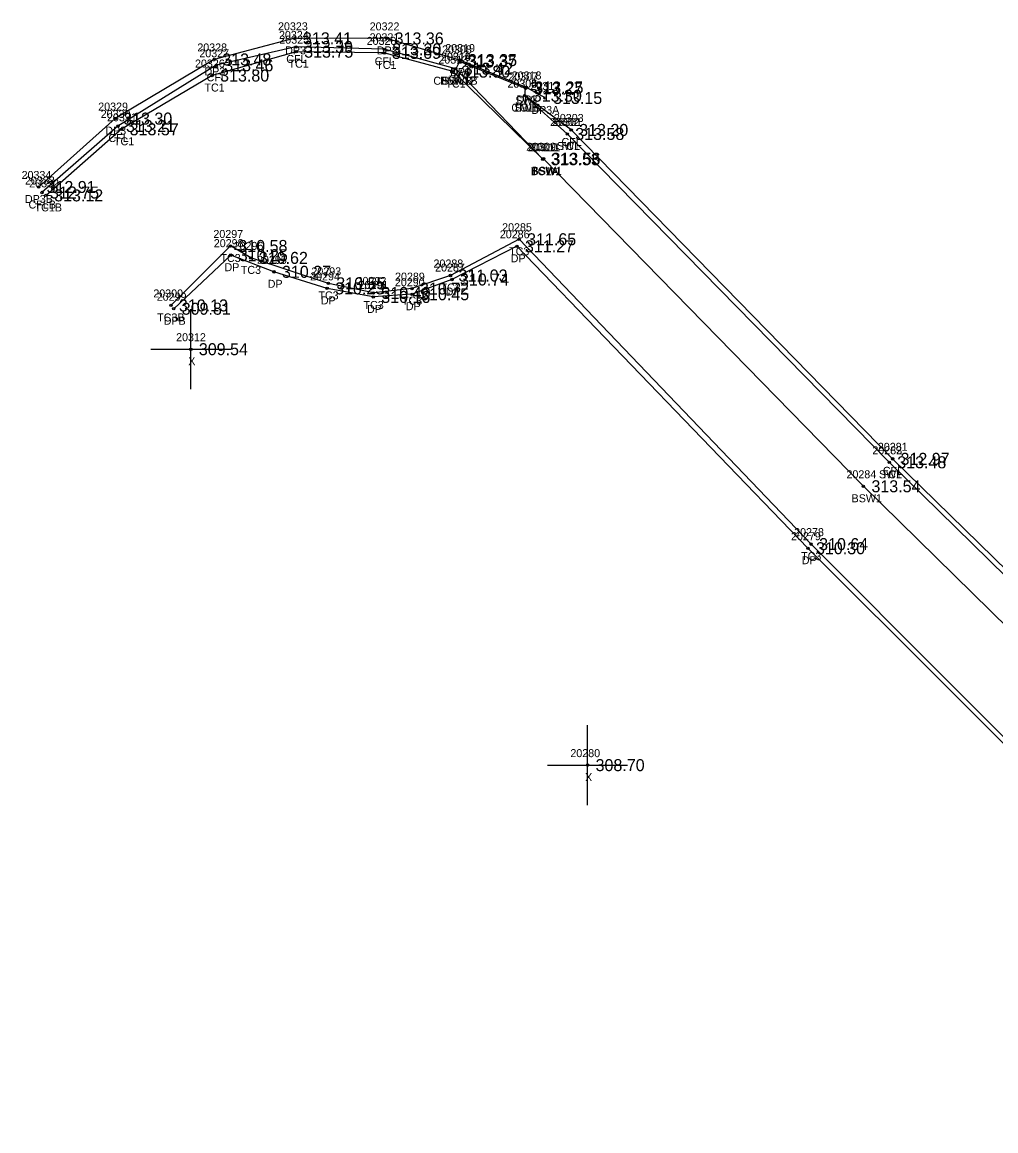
# Model space of a CAD drawing. Extents: x 1970242 to 1971082, y 803104 to 803947.
# Drawn here: x 1970551.6 to 1970673.3, y 803381.9 to 803520.5 of the extents above; entities that cross this region are included whole.
import ezdxf

# ---------------------------------------------------------------- set-up
doc = ezdxf.new("R2010")
doc.units = 0
for name, color, linetype in [('RD_DTM_BkLn2', 7, 'Continuous'), ('RD_EX_Conc', 7, 'Continuous'), ('RD_EX_Conc_txCode', 7, 'Continuous'), ('RD_EX_Driveway', 7, 'Continuous'), ('RD_EX_Driveway_txCode', 7, 'Continuous'), ('RD_EX_Misc', 7, 'Continuous'), ('RD_EX_Misc_txCode', 7, 'Continuous'), ('RD_EX_TX_Conc_ELEV', 7, 'Continuous'), ('RD_EX_TX_Driveway_ELEV', 7, 'Continuous'), ('RD_EX_TX_Misc_ELEV', 7, 'Continuous'), ('RD_SMD_Locator', 7, 'Continuous')]:
    doc.layers.add(name, color=color, linetype=linetype)

msp = doc.modelspace()

# ---------------------------------------------------------------- linework, layer by layer
at = {"layer": 'RD_DTM_BkLn2'}
for points in [[(1970616.66, 803503.34), (1970605.45, 803514.29), (1970596.8, 803516.63), (1970585.83, 803516.78), (1970575.32, 803513.8), (1970564.01, 803507.08), (1970554.57, 803498.82)], [(1970741.86, 803386.33), (1970712.13, 803414.37), (1970659.98, 803465.47), (1970619.72, 803506.5), (1970614.41, 803511.28)], [(1970738.35, 803383.61), (1970734.45, 803382.06), (1970730.21, 803381.92), (1970725.73, 803383.47), (1970721.43, 803385.54), (1970701.8, 803403.54), (1970650.21, 803455.24), (1970613.7, 803493.34), (1970605.12, 803488.81), (1970600.31, 803487.17), (1970595.49, 803486.63), (1970589.85, 803487.83), (1970580.16, 803491.01), (1970577.6, 803492.5), (1970570.17, 803485.07)]]:
    msp.add_lwpolyline(points, dxfattribs=at)
at = {"layer": 'RD_EX_Conc'}
for points in [[(1970605.78, 803514.65), (1970596.84, 803517.08), (1970585.8, 803517.37), (1970575.84, 803515.08), (1970563.55, 803507.49), (1970554.05, 803499.18)], [(1970741.86, 803386.33), (1970712.13, 803414.37), (1970659.98, 803465.47), (1970619.72, 803506.5), (1970614.41, 803511.28), (1970614.52, 803512.19), (1970606.23, 803515.56), (1970605.78, 803514.65)], [(1970738.49, 803383.57), (1970738.35, 803383.61), (1970709.03, 803411.19), (1970656.75, 803462.47), (1970616.75, 803503.4), (1970616.66, 803503.34), (1970605.78, 803514.65)], [(1970742.28, 803386.82), (1970712.72, 803414.79), (1970660.39, 803465.9), (1970620.21, 803507), (1970614.41, 803511.28)]]:
    msp.add_lwpolyline(points, dxfattribs=at)
at = {"layer": 'RD_EX_Driveway'}
for points in [[(1970616.95, 803511), (1970614.61, 803512.31), (1970606.31, 803515.73), (1970597.14, 803518.44), (1970585.68, 803518.45), (1970575.59, 803515.81), (1970563.2, 803508.42), (1970553.62, 803499.87)], [(1970701.56, 803403.12), (1970649.82, 803454.73), (1970613.43, 803492.46), (1970605.31, 803488.31), (1970600.32, 803486.47), (1970595.47, 803486.13), (1970589.7, 803487.2), (1970583.05, 803489.27), (1970577.65, 803491.35), (1970570.52, 803484.66)]]:
    msp.add_lwpolyline(points, dxfattribs=at)
at = {"layer": 'RD_EX_Misc'}
for p, q in [((1970572.66, 803474.6), (1970572.66, 803484.6)), ((1970567.66, 803479.6), (1970577.66, 803479.6)), ((1970622.26, 803422.62), (1970622.26, 803432.62)), ((1970617.26, 803427.62), (1970627.26, 803427.62))]:
    msp.add_line(p, q, dxfattribs=at)
at = {"layer": 'RD_SMD_Locator'}
for centre in [(1970585.68, 803518.45), (1970597.14, 803518.44), (1970585.8, 803517.37), (1970585.83, 803516.78), (1970596.8, 803516.63), (1970596.84, 803517.08), (1970575.59, 803515.81), (1970606.23, 803515.56), (1970606.31, 803515.73), (1970575.84, 803515.08), (1970605.45, 803514.29), (1970605.78, 803514.65), (1970605.78, 803514.65), (1970605.78, 803514.65), (1970575.32, 803513.8), (1970614.41, 803511.28), (1970614.41, 803511.28), (1970614.41, 803511.28), (1970614.52, 803512.19), (1970614.61, 803512.31), (1970616.95, 803511), (1970563.2, 803508.42), (1970563.55, 803507.49), (1970564.01, 803507.08), (1970620.21, 803507), (1970619.72, 803506.5), (1970619.72, 803506.5), (1970616.66, 803503.34), (1970616.66, 803503.34), (1970616.75, 803503.4), (1970553.62, 803499.87), (1970554.05, 803499.18), (1970554.57, 803498.82), (1970613.7, 803493.34), (1970577.6, 803492.5), (1970613.43, 803492.46), (1970577.65, 803491.35), (1970580.16, 803491.01), (1970583.05, 803489.27), (1970589.85, 803487.83), (1970605.12, 803488.81), (1970605.31, 803488.31), (1970589.7, 803487.2), (1970595.47, 803486.13), (1970595.49, 803486.63), (1970600.31, 803487.17), (1970600.32, 803486.47), (1970570.17, 803485.07), (1970570.52, 803484.66), (1970572.66, 803479.6), (1970659.98, 803465.47), (1970659.98, 803465.47), (1970660.39, 803465.9), (1970656.75, 803462.47), (1970649.82, 803454.73), (1970650.21, 803455.24), (1970622.26, 803427.62)]:
    msp.add_circle(centre, 0.15, dxfattribs=at)

# ---------------------------------------------------------------- texts
at = {"layer": 'RD_EX_Conc_txCode'}
for s, p in [('20324', (1970583.68, 803518.37)), ('20325', (1970583.72, 803517.78)), ('20320', (1970594.64, 803517.63)), ('20321', (1970595.01, 803518.08)), ('20327', (1970573.72, 803516.08)), ('20308', (1970604.07, 803516.56)), ('20326', (1970573.18, 803514.8)), ('CFL', (1970584.59, 803515.37)), ('TC1', (1970584.87, 803514.78)), ('CFL', (1970595.64, 803515.08)), ('TC1', (1970595.84, 803514.63)), ('20313', (1970603.61, 803515.29)), ('20316', (1970603.92, 803515.65)), ('20314', (1970603.95, 803515.65)), ('20315', (1970603.95, 803515.65)), ('CFL', (1970574.63, 803513.08)), ('SWL', (1970604.94, 803513.56)), ('20307', (1970612.36, 803513.19)), ('TC1', (1970574.36, 803511.8)), ('CFLA 12', (1970602.98, 803512.65)), ('BSW1B', (1970603.83, 803512.65)), ('SWLB', (1970604.02, 803512.65)), ('TC1', (1970604.49, 803512.29)), ('20306', (1970612.23, 803512.28)), ('20304', (1970612.25, 803512.28)), ('20305', (1970612.25, 803512.28)), ('SWL', (1970613.23, 803510.19)), ('CFLB', (1970612.73, 803509.28)), ('TC1B', (1970612.98, 803509.28)), ('SWL', (1970613.12, 803509.28)), ('20330', (1970561.39, 803508.49)), ('20331', (1970562.18, 803508.08)), ('20302', (1970617.57, 803507.5)), ('20301', (1970617.85, 803507.5)), ('20303', (1970618.05, 803508)), ('CFL', (1970562.35, 803505.49)), ('TC1', (1970563.05, 803505.08)), ('CFL', (1970619, 803505)), ('20309', (1970614.59, 803504.4)), ('20310', (1970614.79, 803504.34)), ('20311', (1970615.11, 803504.34)), ('SWL', (1970618.43, 803504.5)), ('TC1', (1970618.76, 803504.5)), ('TC1A', (1970615.22, 803501.34)), ('BSW1', (1970615.18, 803501.34)), ('BSW1', (1970615.27, 803501.4)), ('20333', (1970551.93, 803500.18)), ('20332', (1970552.45, 803499.82)), ('CFLB', (1970552.37, 803497.18)), ('TC1B', (1970553.13, 803496.82)), ('20285', (1970611.58, 803494.34)), ('20297', (1970575.48, 803493.5)), ('20296', (1970578.01, 803492.01)), ('TC3', (1970612.45, 803491.34)), ('TC3', (1970576.36, 803490.5)), ('20288', (1970603, 803489.81)), ('TC3', (1970578.91, 803489.01)), ('20293', (1970587.73, 803488.83)), ('20289', (1970598.19, 803488.17)), ('20292', (1970593.38, 803487.63)), ('TC3', (1970603.88, 803486.81)), ('20300', (1970567.97, 803486.07)), ('TC3', (1970588.61, 803485.83)), ('TC3', (1970594.25, 803484.63)), ('TC3', (1970599.06, 803485.17)), ('TC3B', (1970568.45, 803483.07)), ('20282', (1970657.87, 803466.47)), ('20283', (1970657.87, 803466.47)), ('20281', (1970658.55, 803466.9)), ('20284', (1970654.63, 803463.47)), ('SWL', (1970658.69, 803463.47)), ('TC1', (1970659.02, 803463.47)), ('CFL', (1970659.18, 803463.9)), ('BSW1', (1970655.27, 803460.47)), ('20278', (1970648.09, 803456.24)), ('TC3', (1970648.96, 803453.24))]:
    msp.add_text(s, height=1, dxfattribs=at).set_placement(p)
at = {"layer": 'RD_EX_Driveway_txCode'}
for s, p in [('20323', (1970583.56, 803519.45)), ('20322', (1970595.02, 803519.44)), ('20328', (1970573.47, 803516.81)), ('DP3', (1970584.45, 803516.45)), ('DP3', (1970595.91, 803516.44)), ('20319', (1970604.47, 803516.73)), ('DP3', (1970574.36, 803513.81)), ('DP3', (1970605.08, 803513.73)), ('20318', (1970612.77, 803513.31)), ('20317', (1970615.11, 803512)), ('DP3', (1970613.38, 803510.31)), ('20329', (1970561.08, 803509.42)), ('DP3A', (1970615.23, 803509)), ('DP3', (1970561.97, 803506.42)), ('20334', (1970551.5, 803500.87)), ('DP3B', (1970551.92, 803497.87)), ('20298', (1970575.53, 803492.35)), ('20286', (1970611.29, 803493.46)), ('20295', (1970580.93, 803490.27)), ('DP', (1970612.65, 803490.46)), ('DP', (1970576.87, 803489.35)), ('20294', (1970587.58, 803488.2)), ('20287', (1970603.2, 803489.31)), ('DP', (1970582.27, 803487.27)), ('20291', (1970593.64, 803487.13)), ('20290', (1970598.17, 803487.47)), ('20299', (1970568.4, 803485.66)), ('DP', (1970604.53, 803486.31)), ('DP', (1970588.92, 803485.2)), ('DP', (1970594.69, 803484.13)), ('DP', (1970599.54, 803484.47)), ('DPB', (1970569.27, 803482.66)), ('20279', (1970647.7, 803455.73)), ('DP', (1970649.04, 803452.73))]:
    msp.add_text(s, height=1, dxfattribs=at).set_placement(p)
at = {"layer": 'RD_EX_Misc_txCode'}
for s, p in [('20312', (1970570.82, 803480.6)), ('X', (1970572.34, 803477.6)), ('20280', (1970620.11, 803428.62)), ('X', (1970621.95, 803425.62))]:
    msp.add_text(s, height=1, dxfattribs=at).set_placement(p)
at = {"layer": 'RD_EX_TX_Conc_ELEV'}
for s, p in [('313.39', (1970586.8, 803516.62)), ('313.75', (1970586.83, 803516.03)), ('313.69', (1970597.8, 803515.88)), ('313.30', (1970597.84, 803516.33)), ('313.46', (1970576.84, 803514.33)), ('313.42', (1970606.78, 803513.9)), ('313.42', (1970606.78, 803513.9)), ('313.42', (1970606.78, 803513.9)), ('313.37', (1970607.23, 803514.81)), ('313.80', (1970576.32, 803513.05)), ('313.80', (1970606.45, 803513.54)), ('313.27', (1970615.52, 803511.44)), ('313.30', (1970615.41, 803510.53)), ('313.30', (1970615.41, 803510.53)), ('313.30', (1970615.41, 803510.53)), ('313.21', (1970564.55, 803506.74)), ('313.57', (1970565.01, 803506.33)), ('313.58', (1970620.72, 803505.75)), ('313.58', (1970620.72, 803505.75)), ('313.20', (1970621.21, 803506.25)), ('313.53', (1970617.66, 803502.59)), ('313.53', (1970617.66, 803502.59)), ('313.56', (1970617.75, 803502.65)), ('312.75', (1970555.05, 803498.43)), ('313.12', (1970555.57, 803498.07)), ('310.58', (1970578.6, 803491.75)), ('311.65', (1970614.7, 803492.59)), ('310.62', (1970581.16, 803490.26)), ('311.03', (1970606.12, 803488.06)), ('310.55', (1970590.85, 803487.08)), ('310.72', (1970601.31, 803486.42)), ('310.40', (1970596.49, 803485.88)), ('310.13', (1970571.17, 803484.32)), ('313.48', (1970660.98, 803464.72)), ('313.48', (1970660.98, 803464.72)), ('312.97', (1970661.39, 803465.15)), ('313.54', (1970657.75, 803461.72)), ('310.64', (1970651.21, 803454.49))]:
    msp.add_text(s, height=1.5, dxfattribs=at).set_placement(p)
at = {"layer": 'RD_EX_TX_Driveway_ELEV'}
for s, p in [('313.41', (1970586.68, 803517.7)), ('313.36', (1970598.14, 803517.69)), ('313.48', (1970576.59, 803515.06)), ('313.35', (1970607.31, 803514.98)), ('313.25', (1970615.61, 803511.56)), ('313.15', (1970617.95, 803510.25)), ('313.30', (1970564.2, 803507.67)), ('312.91', (1970554.62, 803499.12)), ('311.27', (1970614.43, 803491.71)), ('310.25', (1970578.65, 803490.6)), ('310.27', (1970584.05, 803488.52)), ('310.74', (1970606.31, 803487.56)), ('310.23', (1970590.7, 803486.45)), ('310.16', (1970596.47, 803485.38)), ('310.45', (1970601.32, 803485.72)), ('309.81', (1970571.52, 803483.91)), ('310.30', (1970650.82, 803453.98))]:
    msp.add_text(s, height=1.5, dxfattribs=at).set_placement(p)
at = {"layer": 'RD_EX_TX_Misc_ELEV'}
for s, p in [('309.54', (1970573.66, 803478.85)), ('308.70', (1970623.26, 803426.87))]:
    msp.add_text(s, height=1.5, dxfattribs=at).set_placement(p)

doc.saveas('drawing.dxf')
